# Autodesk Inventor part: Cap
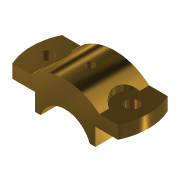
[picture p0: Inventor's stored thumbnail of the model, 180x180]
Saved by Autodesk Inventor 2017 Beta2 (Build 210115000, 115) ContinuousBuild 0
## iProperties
Created: 2009-04
Part Number: Cap
Document SubType Name: Modeling
Designer: Sham
Density: 8.47 g/cm^3
Material: Brass, Soft Yellow
Appearance: Brass - Satin
Author: Sham
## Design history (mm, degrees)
sketch "Sketch1"
  geometry: L1 (-48.857, 23)-(48.857, 23); L2 (48.857, -23)-(-48.857, -23); A1 r 54 centre (0, 0) between (-48.857, 23) and (-48.857, -23); A2 r 54 centre (0, 0) between (48.857, -23) and (48.857, 23); 1 further point
  constraints: 4 end point, 4 point on circle, 2 centre point, 2 coincident, 1 horizontal, 1 parallel, 1 other
  dimensions: "d3" = 54 radius of A1; "d4" = 54 radius of A2; "d5" = 46 distance between parallel lines of L2 L1; "d6" = 23 distance from line of point (0, 0) L1
extrude "Extrusion1" new body sketch "Sketch1" distance "d7" = 12; taper "d8" = 0 deg
sketch "Sketch3"
  geometry: L1 (20.906, 0)-(20.906, -16); L2 (76.906, -0.137)-(76.906, -16.137); L3 (20.906, -16)-(26.23, -16); L4 (71.532, -16.137)-(76.906, -16.137); L5 (76.906, -0.137)-(76.857, 12); L6 (97.714, 0)-(0, 0) reference; L7 (76.857, 12)-(80.606, 12); L8 (17.108, 12)-(20.906, 12); L9 (20.906, 12)-(20.906, 0); L10 (0, 12)-(97.714, 12) reference; A1 r 24 centre (48.857, -24) between (71.532, -16.137) and (26.23, -16); A2 r 48 centre (48.857, -24) between (80.606, 12) and (17.108, 12); 3 further points
  constraints: 16 end point, 4 point on circle, 3 parallel, 3 perpendicular, 2 centre point, 2 coincident, 2 vertical alignment, 1 collinear, 1 midpoint, 1 vertical, 2 other
  dimensions: "d17" = 48 diameter of A1; "d18" = 16 distance of L1.start L1.end; "d19" = 56 distance between parallel lines of L2 L1; "d21" = 8 vertical distance of A1.centre L1.end; "d22" = 48 radius of A2; "d23" = 0 distance from line of L6 L1.start; "d38" = 31.74902 distance of L7.end point (48.857, 12); "d39" = 28 distance from line of point (48.857, 12) L5
extrude "Extrusion2" join sketch "Sketch3" stored distance "d24" = 12; taper "d25" = 0 deg
sketch "Sketch4"
  geometry: 2 further points
  dimensions: "d26" = 78 distance of point (39, 0) point (-39, 0)
hole "Hole1" sketch "Sketch4" at (-39, 0), (39, 0) diameter "d28" = 12; stored, may be unused: countersink angle "d32" = 90 deg, drill point angle "d34" = 118 deg; dims "d29" = 6, "d30" = 4, "d31" = 2, "d33" = 8
sketch "Sketch5"
  geometry: L1 (-31.749, -23)-(-31.749, 23) reference; L2 (-31.749, 14.263)-(-31.749, -14.263); C1 r 6 at (-39, 0) reference; A1 r 16 centre (-39, 0) between (-31.749, -14.263) and (-31.749, 14.263)
  constraints: 2 end point, 2 point on circle, 1 centre point, 1 coincident, 1 collinear, 1 point on line
  dimensions: "d35" = 16 radius of A1
extrude "Extrusion3" cut sketch "Sketch5" distance "d36" = 12; taper "d37" = 0 deg
mirror "Mirror2"
workplane "Work Plane4"
sketch "Sketch6"
  geometry: L1 (-31.749, 0)-(31.749, 0) reference; 1 further point
  dimensions: "d40" = 23 distance from line of L1 point (0, 23)
hole "Hole2" sketch "Sketch6" at (0, 23) diameter "d41" = 6; stored, may be unused: countersink angle "d45" = 90 deg, drill point angle "d47" = 118 deg; dims "d42" = 6, "d43" = 8, "d44" = 16, "d46" = 8
body "Solid1"
